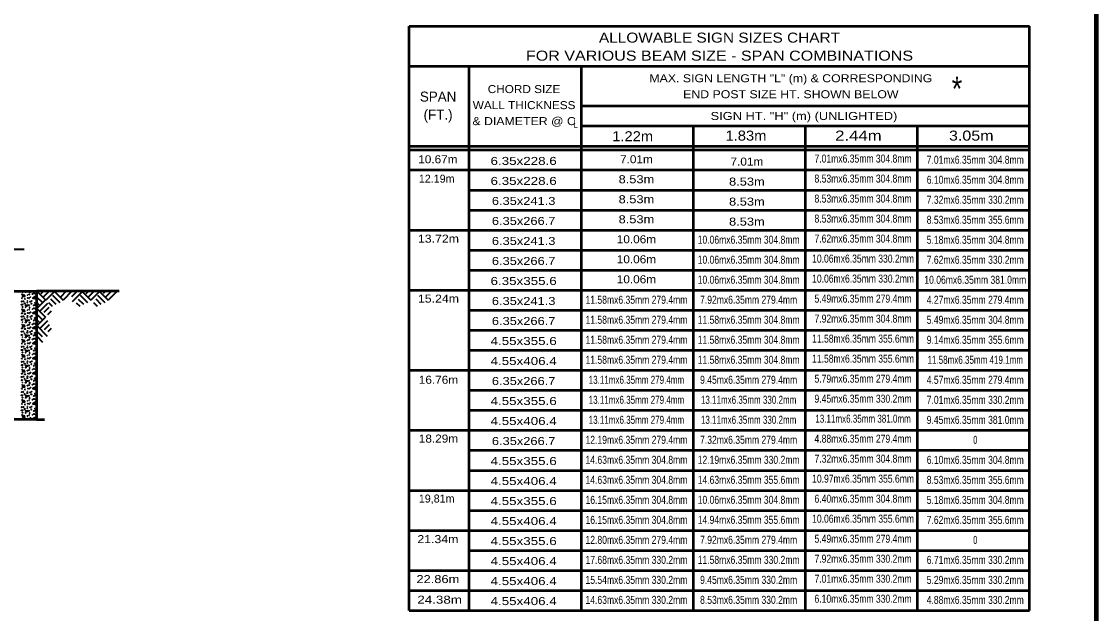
# Model space of a CAD drawing. Extents: x -46 to 809, y -15 to 529.
# Drawn here: x 477.7 to 802.6, y 163.2 to 342 of the extents above; entities that cross this region are included whole.
import ezdxf
from ezdxf.enums import TextEntityAlignment as Align

# ---------------------------------------------------------------- set-up
doc = ezdxf.new("R2010")
doc.units = 0
doc.header["$LTSCALE"] = 1.2
doc.layers.add('1', color=7, linetype='Continuous', lineweight=35)

msp = doc.modelspace()

# ---------------------------------------------------------------- linework, layer by layer
at = {"layer": '1', "lineweight": 158}
msp.add_line((802.618, -3.544), (802.618, 522.556), dxfattribs=at)
at = {"layer": '1', "lineweight": 13}
msp.add_line((802.618, -3.544), (802.618, 522.556), dxfattribs=at)
at = {"layer": '1', "lineweight": 53}
for p, q in [((594.912, 340.599), (782.4, 340.599)), ((594.912, 164.055), (594.912, 340.599)), ((782.4, 164.055), (782.4, 340.599)), ((594.912, 328.503), (782.4, 328.503)), ((613.056, 164.055), (613.056, 328.503)), ((646.92, 164.055), (646.92, 328.503)), ((646.92, 316.455), (782.4, 316.455)), ((646.92, 310.407), (782.4, 310.407)), ((680.784, 164.055), (680.784, 310.407)), ((714.648, 164.055), (714.648, 310.407)), ((748.536, 164.055), (748.536, 310.407)), ((594.912, 304.359), (782.4, 304.359)), ((594.912, 303.159), (782.4, 303.159)), ((594.912, 297.111), (782.4, 297.111)), ((613.056, 291.063), (782.4, 291.063)), ((613.056, 285.015), (782.4, 285.015)), ((594.912, 278.967), (782.4, 278.967)), ((613.056, 272.919), (782.4, 272.919)), ((613.056, 266.871), (782.4, 266.871)), ((507.195, 260.482), (482.283, 260.482)), ((594.912, 260.823), (782.4, 260.823)), ((613.056, 254.775), (782.4, 254.775)), ((613.056, 248.727), (782.4, 248.727)), ((613.056, 242.679), (782.4, 242.679)), ((594.912, 236.631), (782.4, 236.631)), ((613.056, 230.583), (782.4, 230.583)), ((613.056, 224.535), (782.4, 224.535)), ((482.283, 221.77), (484.707, 221.77)), ((594.912, 218.487), (782.4, 218.487)), ((613.056, 212.439), (782.4, 212.439)), ((613.056, 206.391), (782.4, 206.391)), ((594.912, 200.343), (782.4, 200.343)), ((613.056, 194.295), (782.4, 194.295)), ((594.912, 188.247), (782.4, 188.247)), ((613.056, 182.199), (782.4, 182.199)), ((594.912, 176.151), (782.4, 176.151)), ((594.912, 170.103), (782.4, 170.103)), ((594.912, 164.055), (782.4, 164.055))]:
    msp.add_line(p, q, dxfattribs=at)
at = {"layer": '1'}
for p, q in [((473.732, 273.227), (478.532, 273.227)), ((482.331, 260.506), (484.923, 257.913)), ((482.403, 260.434), (485.067, 257.769)), ((484.251, 260.434), (483.579, 259.714)), ((485.979, 260.434), (484.323, 258.754)), ((487.707, 260.434), (485.067, 257.769)), ((487.707, 260.434), (490.299, 257.841)), ((489.435, 260.434), (489.483, 260.482)), ((491.163, 260.434), (489.579, 258.826)), ((492.939, 260.482), (490.299, 257.841)), ((494.427, 260.434), (492.843, 258.826)), ((496.155, 260.434), (492.987, 257.266)), ((496.035, 260.434), (498.699, 257.769)), ((497.859, 260.434), (497.187, 259.714)), ((499.611, 260.434), (497.931, 258.754)), ((501.315, 260.434), (498.699, 257.769)), ((501.315, 260.434), (503.907, 257.841)), ((503.043, 260.434), (502.419, 259.81)), ((504.795, 260.434), (503.187, 258.826)), ((506.499, 260.434), (503.907, 257.841)), ((482.283, 258.247), (481.872, 258.887)), ((482.283, 258.826), (483.939, 257.194)), ((482.283, 258.802), (484.083, 257.05)), ((482.331, 255.322), (484.923, 257.913)), ((482.331, 257.05), (482.955, 256.401)), ((483.435, 254.698), (485.643, 256.93)), ((485.883, 257.074), (486.939, 256.017)), ((486.531, 258.178), (488.067, 256.618)), ((487.083, 259.329), (489.291, 257.122)), ((494.283, 257.002), (495.315, 255.97)), ((494.883, 258.106), (496.443, 256.546)), ((495.435, 259.257), (497.691, 257.05)), ((499.515, 257.074), (500.547, 256.017)), ((500.139, 258.178), (501.699, 256.618)), ((500.691, 259.329), (502.923, 257.122)), ((482.283, 253.687), (481.872, 254.327)), ((482.331, 255.322), (484.995, 252.681)), ((482.331, 253.594), (484.011, 251.938)), ((484.587, 254.145), (486.123, 255.681)), ((485.691, 253.498), (486.747, 254.554)), ((482.331, 250.018), (484.995, 252.681)), ((482.331, 251.866), (483.027, 251.194)), ((483.507, 249.442), (485.715, 251.698)), ((484.659, 248.889), (486.195, 250.425)), ((482.283, 249.127), (481.872, 249.767)), ((482.331, 250.138), (485.499, 246.97)), ((482.331, 248.434), (483.939, 246.826)), ((485.763, 248.29), (486.795, 249.322)), ((482.283, 244.567), (481.872, 245.207)), ((482.331, 246.874), (484.059, 245.145)), ((482.283, 240.007), (481.872, 240.647)), ((482.283, 235.447), (481.872, 236.087)), ((482.283, 230.887), (481.872, 231.527)), ((482.283, 226.327), (481.872, 226.967)), ((482.282, 221.77), (481.872, 222.407))]:
    msp.add_line(p, q, dxfattribs=at)
at = {"layer": '1', "lineweight": 53}
msp.add_lwpolyline([(453.267, 260.482), (482.283, 260.482), (482.283, 221.77), (474.699, 221.77), (473.883, 224.05), (472.227, 219.49), (471.411, 221.77), (464.139, 221.77), (463.323, 219.49), (461.667, 224.05), (460.827, 221.77), (453.267, 221.77)], close=True, dxfattribs=at)
msp.add_lwpolyline([(453.267, 260.482), (482.283, 260.482), (482.283, 221.77), (474.699, 221.77), (473.883, 224.05), (472.227, 219.49), (471.411, 221.77), (464.139, 221.77), (463.323, 219.49), (461.667, 224.05), (460.827, 221.77), (453.267, 221.77)], close=True, dxfattribs=at)
at = {"layer": '1'}
for points in [[(478.44, 259.487), (477.984, 259.007), (478.68, 258.959), (478.44, 259.439)], [(481.92, 258.863), (481.128, 258.431), (482.283, 258.219)], [(478.44, 254.927), (477.984, 254.447), (478.68, 254.399), (478.44, 254.879)], [(481.92, 254.303), (481.128, 253.871), (482.283, 253.659)], [(478.44, 250.367), (477.984, 249.887), (478.68, 249.839), (478.44, 250.319)], [(481.92, 249.743), (481.128, 249.311), (482.283, 249.099)], [(478.44, 245.807), (477.984, 245.327), (478.68, 245.279), (478.44, 245.759)], [(481.92, 245.183), (481.128, 244.751), (482.283, 244.539)], [(478.44, 241.247), (477.984, 240.767), (478.68, 240.719), (478.44, 241.199)], [(481.92, 240.623), (481.128, 240.191), (482.283, 239.979)], [(478.44, 236.687), (477.984, 236.207), (478.68, 236.159), (478.44, 236.639)], [(481.92, 236.063), (481.128, 235.631), (482.283, 235.419)], [(478.44, 232.127), (477.984, 231.647), (478.68, 231.599), (478.44, 232.079)], [(481.92, 231.503), (481.128, 231.071), (482.283, 230.859)], [(478.44, 227.567), (477.984, 227.087), (478.68, 227.039), (478.44, 227.519)], [(481.92, 226.943), (481.128, 226.511), (482.283, 226.299)], [(478.44, 223.007), (477.984, 222.527), (478.68, 222.479), (478.44, 222.959)], [(481.92, 222.383), (481.128, 221.951), (482.118, 221.77)]]:
    msp.add_lwpolyline(points, dxfattribs=at)
for points in [[(478.776, 256.415), (480.024, 256.271), (479.208, 255.983)], [(478.776, 251.855), (480.024, 251.711), (479.208, 251.423)], [(478.776, 247.295), (480.024, 247.151), (479.208, 246.863)], [(478.776, 242.735), (480.024, 242.591), (479.208, 242.303)], [(478.776, 238.175), (480.024, 238.031), (479.208, 237.743)], [(478.776, 233.615), (480.024, 233.471), (479.208, 233.183)], [(478.776, 229.055), (480.024, 228.911), (479.208, 228.623)], [(478.776, 224.495), (480.024, 224.351), (479.208, 224.063)]]:
    msp.add_lwpolyline(points, close=True, dxfattribs=at)
for centre in [(478.022, 260.282), (478.992, 260.234), (480.185, 260.139), (482.22, 260.298), (477.774, 257.392), (477.847, 258.395), (477.911, 259.572), (478.276, 257.456), (478.674, 256.836), (478.785, 258.188), (479.485, 257.106), (479.517, 259.317), (479.549, 257.583), (479.644, 258.458), (480.058, 259.524), (480.058, 258.411), (480.376, 257.329), (480.439, 258.697), (480.71, 256.708), (480.853, 257.583), (481.028, 259.635), (481.505, 259.868), (481.759, 256.979), (481.982, 259.715), (477.75, 256.419), (477.847, 253.835), (477.911, 255.012), (478.022, 256.438), (478.022, 255.722), (478.785, 253.628), (478.992, 255.674), (479.517, 254.757), (479.644, 253.898), (480.058, 254.964), (480.058, 253.851), (480.185, 255.579), (480.439, 254.137), (481.028, 255.075), (481.425, 256.215), (481.505, 255.308), (481.807, 256.39), (481.982, 255.155), (482.22, 255.738), (477.75, 251.859), (477.774, 252.832), (477.911, 250.452), (478.022, 251.878), (478.022, 251.162), (478.276, 252.896), (478.674, 252.276), (478.992, 251.114), (479.485, 252.546), (479.517, 250.197), (479.549, 253.023), (480.058, 250.404), (480.185, 251.019), (480.376, 252.769), (480.71, 252.148), (480.853, 253.023), (481.028, 250.515), (481.425, 251.655), (481.505, 250.748), (481.759, 252.419), (481.807, 251.83), (481.982, 250.595), (482.22, 251.178), (477.75, 247.299), (477.774, 248.272), (477.847, 249.275), (478.022, 247.318), (478.276, 248.336), (478.674, 247.716), (478.785, 249.068), (479.485, 247.986), (479.549, 248.463), (479.644, 249.338), (480.058, 249.291), (480.376, 248.209), (480.439, 249.577), (480.71, 247.588), (480.853, 248.463), (481.425, 247.095), (481.759, 247.859), (481.807, 247.27), (477.774, 243.712), (477.847, 244.715), (477.911, 245.892), (478.022, 246.602), (478.276, 243.776), (478.785, 244.508), (478.992, 246.554), (479.517, 245.637), (479.549, 243.903), (479.644, 244.778), (480.058, 245.844), (480.058, 244.731), (480.185, 246.459), (480.376, 243.649), (480.439, 245.017), (480.853, 243.903), (481.028, 245.955), (481.505, 246.188), (481.982, 246.035), (482.22, 246.618), (477.75, 242.739), (477.911, 241.332), (478.022, 242.758), (478.022, 242.042), (478.674, 243.156), (478.992, 241.994), (479.485, 243.426), (479.517, 241.077), (480.058, 241.284), (480.185, 241.899), (480.439, 240.457), (480.71, 243.028), (481.028, 241.395), (481.425, 242.535), (481.505, 241.628), (481.759, 243.299), (481.807, 242.71), (481.982, 241.475), (482.22, 242.058), (477.75, 238.179), (477.774, 239.152), (477.847, 240.155), (478.022, 238.198), (478.022, 237.482), (478.276, 239.216), (478.674, 238.596), (478.785, 239.948), (478.992, 237.434), (479.485, 238.866), (479.549, 239.343), (479.644, 240.218), (480.058, 240.171), (480.185, 237.339), (480.376, 239.089), (480.71, 238.468), (480.853, 239.343), (481.425, 237.975), (481.759, 238.739), (481.807, 238.15), (482.22, 237.498), (477.774, 234.592), (477.847, 235.595), (477.911, 236.772), (478.276, 234.656), (478.674, 234.036), (478.785, 235.388), (479.485, 234.306), (479.517, 236.517), (479.549, 234.783), (479.644, 235.658), (480.058, 236.724), (480.058, 235.611), (480.376, 234.529), (480.439, 235.897), (480.71, 233.908), (480.853, 234.783), (481.028, 236.835), (481.505, 237.068), (481.759, 234.179), (481.982, 236.915), (477.75, 233.619), (477.847, 231.035), (477.911, 232.212), (478.022, 233.638), (478.022, 232.922), (478.785, 230.828), (478.992, 232.874), (479.517, 231.957), (479.644, 231.098), (480.058, 232.164), (480.058, 231.051), (480.185, 232.779), (480.439, 231.337), (481.028, 232.275), (481.425, 233.415), (481.505, 232.508), (481.807, 233.59), (481.982, 232.355), (482.22, 232.938), (477.75, 229.059), (477.774, 230.032), (477.911, 227.652), (478.022, 229.078), (478.022, 228.362), (478.276, 230.096), (478.674, 229.476), (478.992, 228.314), (479.485, 229.746), (479.549, 230.223), (480.058, 227.604), (480.185, 228.219), (480.376, 229.969), (480.71, 229.348), (480.853, 230.223), (481.028, 227.715), (481.425, 228.855), (481.505, 227.948), (481.759, 229.619), (481.807, 229.03), (481.982, 227.795), (482.22, 228.378), (477.75, 224.499), (477.774, 225.472), (477.847, 226.475), (478.022, 224.518), (478.276, 225.536), (478.674, 224.916), (478.785, 226.268), (479.485, 225.186), (479.517, 227.397), (479.549, 225.663), (479.644, 226.538), (480.058, 226.491), (480.376, 225.409), (480.439, 226.777), (480.71, 224.788), (480.853, 225.663), (481.425, 224.295), (481.759, 225.059), (481.807, 224.47), (477.847, 221.915), (477.911, 223.092), (478.022, 223.802), (478.992, 223.754), (479.517, 222.837), (479.644, 221.978), (480.058, 223.044), (480.058, 221.931), (480.185, 223.659), (480.439, 222.217), (481.028, 223.155), (481.505, 223.388), (481.982, 223.235), (482.22, 223.818)]:
    msp.add_circle(centre, 0.0318, dxfattribs=at)
for centre in [(482.252, 257.186), (482.252, 252.626), (482.252, 248.066), (482.252, 243.506), (482.252, 238.946), (482.252, 234.386), (482.252, 229.826), (482.252, 225.266)]:
    msp.add_arc(centre, 0.0318, 12.37307, 347.62693, dxfattribs=at)

# ---------------------------------------------------------------- texts
for s, height, width, p in [('ALLOWABLE SIGN SIZES CHART', 3.024, 1.15, (688.68, 335.588)), ('FOR VARIOUS BEAM SIZE - SPAN COMBINATIONS', 3.024, 1.2, (688.683, 330.14)), ('MAX. SIGN LENGTH "L" (m) & CORRESPONDING', 2.419, 1.15, (710.237, 323.609)), ('*', 7.258, 0.85, (760.449, 318.038)), ('CHORD SIZE', 2.419, 1.1, (629.596, 320.34)), ('END POST SIZE HT. SHOWN BELOW', 2.419, 1.15, (710.237, 318.79)), ('WALL THICKNESS', 2.419, 1.1, (629.627, 315.492)), ('& DIAMETER @ C', 2.419, 1.15, (629.626, 310.668)), ('L', 2.419, 0.75, (645.175, 309.878)), ('SIGN HT. "H" (m) (UNLIGHTED)', 2.419, 1.2, (714.209, 312.227)), ('1.22m', 3.024, 1.1, (662.428, 305.799)), ('1.83m', 3.024, 1.1, (696.676, 305.991)), ('2.44m', 3.024, 1.25, (730.653, 305.991)), ('3.05m', 3.024, 1.2, (764.769, 305.991)), ('10.67m', 2.419, 1.1, (603.558, 299.141)), ('6.35x228.6', 2.419, 1.25, (629.481, 298.641)), ('7.01m', 2.419, 1.1, (663.572, 299.154)), ('7.01m', 2.419, 1.1, (696.952, 298.443)), ('7.01mx6.35mm 304.8mm', 2.419, 0.8, (732.062, 299.353)), ('7.01mx6.35mm 304.8mm', 2.419, 0.8, (765.975, 298.998)), ('8.53mx6.35mm 304.8mm', 2.419, 0.8, (732.061, 293.31)), ('6.35x228.6', 2.419, 1.25, (629.481, 292.598)), ('8.53m', 2.419, 1.2, (663.571, 293.111)), ('8.53m', 2.419, 1.2, (696.952, 292.4)), ('6.10mx6.35mm 304.8mm', 2.419, 0.8, (765.975, 292.955)), ('8.53m', 2.419, 1.2, (663.571, 287.067)), ('8.53mx6.35mm 304.8mm', 2.419, 0.8, (732.061, 287.267)), ('7.32mx6.35mm 330.2mm', 2.419, 0.8, (765.975, 286.911)), ('6.35x241.3', 2.419, 1.2, (629.481, 286.555)), ('8.53m', 2.419, 1.2, (696.952, 286.357)), ('6.35x266.7', 2.419, 1.2, (629.481, 280.512)), ('8.53m', 2.419, 1.2, (663.571, 281.024)), ('8.53m', 2.419, 1.2, (696.952, 280.314)), ('8.53mx6.35mm 304.8mm', 2.419, 0.8, (732.061, 281.223)), ('8.53mx6.35mm 355.6mm', 2.419, 0.8, (765.975, 280.868)), ('13.72m', 2.419, 1.15, (603.736, 275.165)), ('6.35x241.3', 2.419, 1.2, (629.481, 274.469)), ('10.06m', 2.419, 1.1, (663.571, 274.981)), ('10.06mx6.35mm 304.8mm', 2.419, 0.8, (697.48, 274.843)), ('7.62mx6.35mm 304.8mm', 2.419, 0.8, (732.061, 275.18)), ('5.18mx6.35mm 304.8mm', 2.419, 0.8, (765.975, 274.825)), ('6.35x266.7', 2.419, 1.2, (629.481, 268.425)), ('10.06m', 2.419, 1.1, (663.571, 268.938)), ('10.06mx6.35mm 304.8mm', 2.419, 0.8, (697.48, 268.8)), ('10.06mx6.35mm 330.2mm', 2.419, 0.8, (732.062, 269.137)), ('7.62mx6.35mm 330.2mm', 2.419, 0.8, (765.975, 268.782)), ('6.35x355.6', 2.419, 1.25, (629.481, 262.382)), ('10.06m', 2.419, 1.1, (663.571, 262.895)), ('10.06mx6.35mm 304.8mm', 2.419, 0.8, (697.48, 262.757)), ('10.06mx6.35mm 330.2mm', 2.419, 0.8, (732.062, 263.094)), ('10.06mx6.35mm 381.0mm', 2.419, 0.8, (765.975, 262.739)), ('15.24m', 2.419, 1.15, (603.736, 257.05)), ('6.35x241.3', 2.419, 1.2, (629.481, 256.339)), ('11.58mx6.35mm 279.4mm', 2.419, 0.8, (663.572, 256.708)), ('7.92mx6.35mm 279.4mm', 2.419, 0.8, (697.48, 256.714)), ('5.49mx6.35mm 279.4mm', 2.419, 0.8, (732.061, 257.051)), ('4.27mx6.35mm 279.4mm', 2.419, 0.8, (765.975, 256.695)), ('7.92mx6.35mm 304.8mm', 2.419, 0.8, (732.061, 251.007)), ('6.35x266.7', 2.419, 1.2, (629.481, 250.296)), ('11.58mx6.35mm 279.4mm', 2.419, 0.8, (663.572, 250.664)), ('11.58mx6.35mm 304.8mm', 2.419, 0.8, (697.48, 250.67)), ('5.49mx6.35mm 304.8mm', 2.419, 0.8, (765.975, 250.652)), ('11.58mx6.35mm 279.4mm', 2.419, 0.8, (663.572, 244.621)), ('11.58mx6.35mm 304.8mm', 2.419, 0.8, (697.48, 244.627)), ('11.58mx6.35mm 355.6mm', 2.419, 0.8, (732.062, 244.964)), ('9.14mx6.35mm 355.6mm', 2.419, 0.8, (765.975, 244.609)), ('4.55x355.6', 2.419, 1.25, (629.481, 244.253)), ('4.55x406.4', 2.419, 1.25, (629.481, 238.209)), ('11.58mx6.35mm 279.4mm', 2.419, 0.8, (663.572, 238.578)), ('11.58mx6.35mm 304.8mm', 2.419, 0.8, (697.48, 238.584)), ('11.58mx6.35mm 355.6mm', 2.419, 0.8, (732.062, 238.921)), ('11.58mx6.35mm 419.1mm', 2.419, 0.75, (765.975, 238.566)), ('16.76m', 2.419, 1.1, (603.736, 232.541)), ('6.35x266.7', 2.419, 1.2, (629.481, 232.166)), ('13.11mx6.35mm 279.4mm', 2.419, 0.75, (663.571, 232.535)), ('9.45mx6.35mm 279.4mm', 2.419, 0.8, (697.48, 232.541)), ('5.79mx6.35mm 279.4mm', 2.419, 0.8, (732.061, 232.878)), ('4.57mx6.35mm 279.4mm', 2.419, 0.8, (765.975, 232.523)), ('4.55x355.6', 2.419, 1.25, (629.481, 226.123)), ('13.11mx6.35mm 279.4mm', 2.419, 0.75, (663.571, 226.492)), ('13.11mx6.35mm 330.2mm', 2.419, 0.75, (697.48, 226.498)), ('9.45mx6.35mm 330.2mm', 2.419, 0.8, (732.061, 226.835)), ('7.01mx6.35mm 330.2mm', 2.419, 0.8, (765.975, 226.479)), ('4.55x406.4', 2.419, 1.25, (629.481, 220.08)), ('13.11mx6.35mm 279.4mm', 2.419, 0.75, (663.571, 220.448)), ('13.11mx6.35mm 330.2mm', 2.419, 0.75, (697.48, 220.454)), ('13.11mx6.35mm 381.0mm', 2.419, 0.75, (732.062, 220.791)), ('9.45mx6.35mm 381.0mm', 2.419, 0.8, (765.975, 220.436)), ('18.29m', 2.419, 1.1, (603.736, 214.781)), ('6.35x266.7', 2.419, 1.2, (629.481, 214.037)), ('12.19mx6.35mm 279.4mm', 2.419, 0.8, (663.572, 214.405)), ('7.32mx6.35mm 279.4mm', 2.419, 0.8, (697.48, 214.411)), ('4.88mx6.35mm 279.4mm', 2.419, 0.8, (732.062, 214.748)), ('0', 2.419, 0.55, (765.975, 214.393)), ('4.55x355.6', 2.419, 1.25, (629.481, 207.993)), ('14.63mx6.35mm 304.8mm', 2.419, 0.8, (663.571, 208.362)), ('12.19mx6.35mm 330.2mm', 2.419, 0.8, (697.48, 208.368)), ('7.32mx6.35mm 304.8mm', 2.419, 0.8, (732.062, 208.705)), ('6.10mx6.35mm 304.8mm', 2.419, 0.8, (765.975, 208.35)), ('14.63mx6.35mm 304.8mm', 2.419, 0.8, (663.571, 202.319)), ('14.63mx6.35mm 355.6mm', 2.419, 0.8, (697.48, 202.325)), ('10.97mx6.35mm 355.6mm', 2.419, 0.8, (732.062, 202.662)), ('8.53mx6.35mm 355.6mm', 2.419, 0.8, (765.975, 202.307)), ('4.55x406.4', 2.419, 1.25, (629.481, 201.95)), ('4.55x355.6', 2.419, 1.25, (629.481, 195.907)), ('16.15mx6.35mm 304.8mm', 2.419, 0.8, (663.572, 196.276)), ('10.06mx6.35mm 304.8mm', 2.419, 0.8, (697.48, 196.282)), ('6.40mx6.35mm 304.8mm', 2.419, 0.8, (732.061, 196.619)), ('5.18mx6.35mm 304.8mm', 2.419, 0.8, (765.975, 196.263)), ('4.55x406.4', 2.419, 1.25, (629.481, 189.864)), ('16.15mx6.35mm 304.8mm', 2.419, 0.8, (663.572, 190.232)), ('14.94mx6.35mm 355.6mm', 2.419, 0.8, (697.48, 190.238)), ('10.06mx6.35mm 355.6mm', 2.419, 0.8, (732.062, 190.575)), ('7.62mx6.35mm 355.6mm', 2.419, 0.8, (765.975, 190.22)), ('21.34m', 2.419, 1.15, (603.558, 184.411)), ('4.55x355.6', 2.419, 1.25, (629.481, 183.821)), ('12.80mx6.35mm 279.4mm', 2.419, 0.8, (663.571, 184.189)), ('7.92mx6.35mm 279.4mm', 2.419, 0.8, (697.48, 184.195)), ('5.49mx6.35mm 279.4mm', 2.419, 0.8, (732.061, 184.532)), ('0', 2.419, 0.55, (765.975, 184.177)), ('4.55x406.4', 2.419, 1.25, (629.481, 177.777)), ('17.68mx6.35mm 330.2mm', 2.419, 0.8, (663.572, 178.146)), ('11.58mx6.35mm 330.2mm', 2.419, 0.8, (697.48, 178.152)), ('7.92mx6.35mm 330.2mm', 2.419, 0.8, (732.062, 178.489)), ('6.71mx6.35mm 330.2mm', 2.419, 0.8, (765.975, 178.134)), ('22.86m', 2.419, 1.2, (603.558, 172.335)), ('4.55x406.4', 2.419, 1.25, (629.481, 171.734)), ('15.54mx6.35mm 330.2mm', 2.419, 0.8, (663.571, 172.103)), ('9.45mx6.35mm 330.2mm', 2.419, 0.8, (697.48, 172.109)), ('7.01mx6.35mm 330.2mm', 2.419, 0.8, (732.062, 172.446)), ('5.29mx6.35mm 330.2mm', 2.419, 0.8, (765.975, 172.091)), ('24.38m', 2.419, 1.25, (604.091, 166.119)), ('4.55x406.4', 2.419, 1.25, (629.481, 165.691)), ('14.63mx6.35mm 330.2mm', 2.419, 0.8, (663.571, 166.06)), ('8.53mx6.35mm 330.2mm', 2.419, 0.8, (697.48, 166.066)), ('6.10mx6.35mm 330.2mm', 2.419, 0.8, (732.062, 166.403)), ('4.88mx6.35mm 330.2mm', 2.419, 0.8, (765.975, 166.047))]:
    msp.add_text(s, height=height, dxfattribs=dict(at, width=width)).set_placement(p, align=Align.CENTER)
for s, height, p in [('SPAN', 3.024, (603.629, 317.771)), ('(FT.)', 3.024, (603.62, 312.323)), ('12.19m', 2.419, (603.203, 293.28)), ('19,81m', 2.419, (603.203, 196.666))]:
    msp.add_text(s, height=height, dxfattribs=at).set_placement(p, align=Align.CENTER)

doc.saveas('drawing.dxf')
